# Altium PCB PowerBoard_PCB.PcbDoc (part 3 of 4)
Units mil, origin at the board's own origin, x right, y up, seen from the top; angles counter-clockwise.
Board outline 9251.97 x 3346.46 mil, 6 copper layers (Top Layer, Signal Layer 1, Signal Layer 2, Signal Layer 3, Signal Layer 4, Bottom Layer), stack 65.8 mil thick; 241 components, 145 nets, 894 pads, 120 vias.
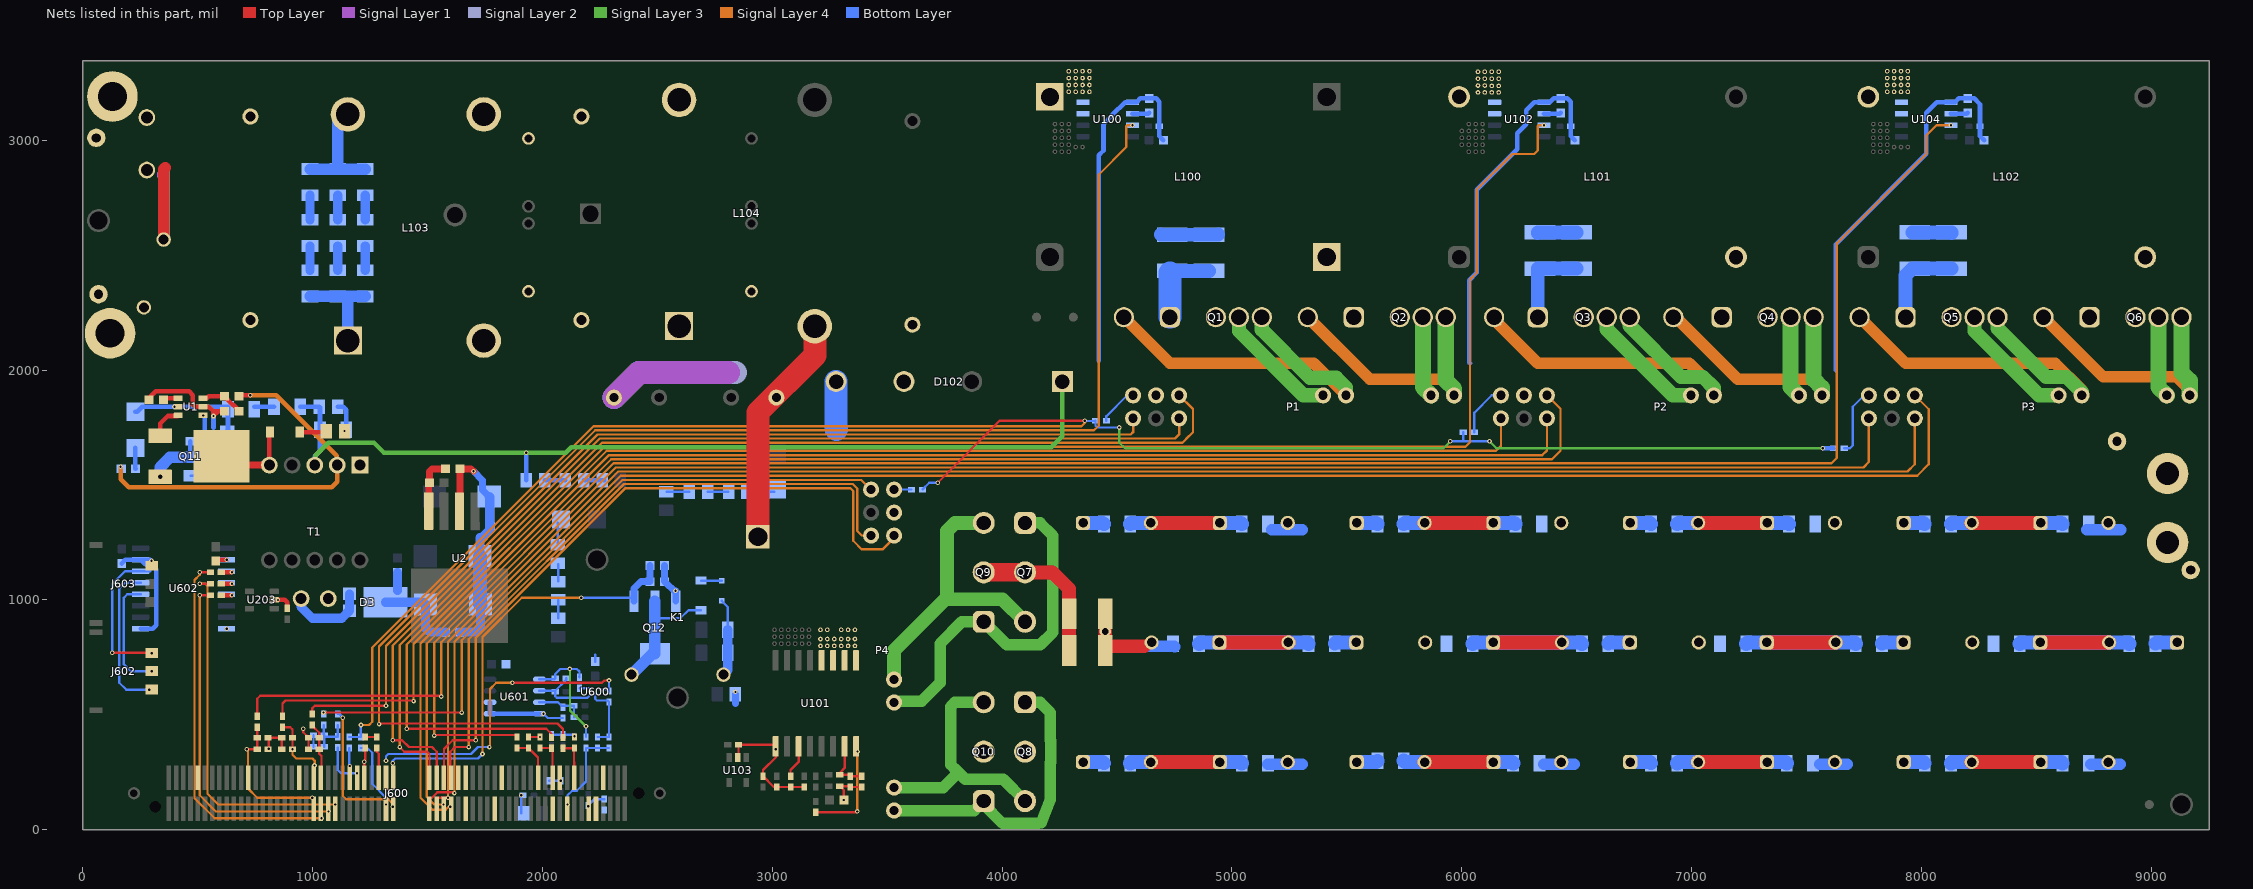
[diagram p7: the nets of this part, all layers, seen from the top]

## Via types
v1: diameter 20, hole 10, Top Layer to Bottom Layer, 116 vias
v2: diameter 30, hole 20, Top Layer to Bottom Layer, 3 vias
v3: diameter 50, hole 30, Top Layer to Bottom Layer, 1 vias

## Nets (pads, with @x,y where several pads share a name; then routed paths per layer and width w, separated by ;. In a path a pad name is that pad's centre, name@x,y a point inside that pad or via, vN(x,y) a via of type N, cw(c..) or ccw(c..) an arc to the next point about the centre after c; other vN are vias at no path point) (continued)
F1: C611.1 J600.77 R618.1 R631.2 | length 248.2
  Top Layer w10: R618.1@1000,456.38 1000,451.85 1029.97,421.88 R631.2@1029.97,400 C611.1@1029.97,349.84 1029.97,330.72 1040,320.69 1040,229.33 J600.77@1036.73,226.06
F2: C612.1 J600.79 R620.1 R632.2 | length 286.5
  Top Layer w10: R620.1@870,446.38 903.62,446.38 913.62,436.38 C612.1@913.62,400 v1(913.62,350)
  Signal Layer 4 w10: v1(913.62,350) 913.62,326.38 930,310 1000,310 1010,300 1010,280.98 v1(1009.02,280)
  Signal Layer 2 w10: v1(1009.02,280) v1@1010,280
F3: C613.1 J600.80 R624.1 R633.2 | length 652.9
  Top Layer w10: v1@720,350 C613.1@760,350 R633.2@760,400 R624.1@760,446.38 ; v1(1000,140) 1005.24,134.76 J600.80@1005.24,92.2
  Signal Layer 4 w10: v1@720,350 720,180 760,140 v1(1000,140)
  other v1: 715,350
F4: C618.1 R635.1 R636.2 R640.1 R643.2 | length 207.5
  Bottom Layer w10: R635.1@1050,456.38 1050,413.28 R636.2@1051.62,411.65 ; C618.1@1051.62,361.65 R636.2@1051.62,411.65 ; R643.2@1110,456.38 R640.1@1110,405.28 1058,405.28 R636.2@1051.62,411.65
G_AC_I: C602.1 J600.59 U600.6 | length 1363.2
  Top Layer w10: v1(1870,640) 2260,640 2270,650 v1(2290,650)
  Signal Layer 4 w10: v1(1770,360) 1772.48,362.48 1772.48,612.48 1800,640 v1(1870,640)
  Bottom Layer w10: v1(1320,300) 1320,320 1330,330 1690,330 1720,360 v1(1770,360) ; U600.6@2249.69,611.81 2281.81,611.81 C602.1@2290,603.62 v1(2290,650)
HVBUS: C1.1 C3.1 C5.1 C7.1 C9.1 C11.1 C13.1 C15.1 C17.1 C19.1 C21.1 C23.1 C27.1 C28.1 C29.1 C30.1 C31.1 C32.1 C33.1 C34.1 C36.1 D102.1 pad.1@9070,1550 Q1.1 Q3.1 Q5.1 Q7.2 Q9.2 R1.2 R3.2 R5.2 R7.2 R9.2 R11.2 R13.2 R15.2 R17.2 R19.2 R21.2 R23.2 R38.2 R40.2 R602.2 T1.3 TP100.1 | length 7000.1
  Top Layer w60: Q7.2@4100,1120 4220,1120 4291.26,1048.74 C27.1@4291.26,940 C28.1@4291.26,780
  Top Layer w80: Q9.2@3920,1120 Q7.2@4100,1120
  Signal Layer 3 w20: T1.3@1010,1586.69 1012.01,1588.7 1012.01,1626.63 1068.49,1683.11 1268.12,1683.11 1311.23,1640 v1(1930,1640) 2101.42,1640 2125.67,1664.25 4214.25,1664.25 4262.13,1712.13 D102.1@4262.13,1950
  Bottom Layer w20: R38.2@947.09,1840 C36.1@1030,1840 1032.91,1837.09 R40.2@1032.91,1740 1032.91,1647.54 1010,1624.62 T1.3@1010,1586.69 ; R602.2@1930,1520 v1(1930,1640)
  Bottom Layer w60: C17.1@4352.36,295 4437.91,295 R17.2@4442.91,290 ; C1.1@4352.36,1335 4437.91,1335 R1.2@4442.91,1330 ; C29.1@4730,2421.26 C29.1@4740,2431.26 C30.1@4900,2431.26 ; R15.2@5447.09,810 5452.09,815 C15.1@5540.64,815 ; C19.1@5542.36,295 5627.91,295 R19.2@5632.91,300 ; C3.1@5542.36,1335 5627.91,1335 R3.2@5632.91,1330 ; Q3.1@6330,2230 6330,2441.26 C32.1@6500,2441.26 ; R13.2@6637.09,810 6642.09,815 C13.1@6730.64,815 ; C21.1@6732.36,295 6817.91,295 R21.2@6822.91,290 ; C5.1@6732.36,1335 6817.91,1335 R5.2@6822.91,1330 ; R11.2@7827.09,810 7832.09,815 C11.1@7920.64,815 ; C23.1@7922.36,295 8007.91,295 R23.2@8012.91,290 ; C7.1@7922.36,1335 8007.91,1335 R7.2@8012.91,1330 ; Q5.1@7930,2230 7930,2411.26 7960,2441.26 C34.1@8130,2441.26 ; R9.2@9017.09,810 9022.09,815 C9.1@9110.64,815
  Bottom Layer w100: Q1.1@4730,2230 C29.1@4730,2421.26
L100_CS: R600.1 U100.7 | length 6095.1
  Top Layer w10: v1(1290,460) 1292.87,462.87 2066.34,462.87 2090,439.21 R600.1@2090,401.81
  Signal Layer 4 w10: v1(1290,460) 1290,797.87 2230,1737.87 4400,1737.87 4420,1757.87 4420,2850 4540,2970 4540,3060 4545,3065 v1(4567.28,3065)
L101_CS: R603.1 U102.7 | length 7592.1
  Top Layer w10: v1(1410,440) 2017.56,440 2040,417.56 R603.1@2040,401.81
  Signal Layer 4 w10: v1(1410,440) 1410,806.38 2270,1666.38 6015.67,1666.38 6035.29,1686 6035.29,2393.95 6065,2423.66 6065,2785 6220,2940 6314.91,2940 6330,2955.09 6330,3060 6335,3065 v1(6357.28,3065)
L102_CS: R608.1 U104.7 | length 8892.4
  Top Layer w10: v1(1530,410) 1532.87,412.87 1880.75,412.87 R608.1@1890,403.62
  Signal Layer 4 w10: v1(1530,410) 1530,814.25 2310,1594.25 7607.56,1594.25 7630.91,1617.6 7630.91,2550.91 8020,2940 8020,3020 8065,3065 v1(8127.28,3065)
NetC1_2: C1.2 C2.1 R1.1 R2.2 | length 1389.1
  Top Layer w62: C1.2@4647.64,1335 C2.1@4947.36,1335
  Signal Layer 1 w62: C1.2@4647.64,1335 C2.1@4947.36,1335
  Signal Layer 2 w62: C1.2@4647.64,1335 C2.1@4947.36,1335
  Bottom Layer w62: R1.1@4557.09,1330 4562.09,1335 C1.2@4647.64,1335 C2.1@4947.36,1335 5037.91,1335 R2.2@5042.91,1330
NetC3_2: C3.2 C4.1 R3.1 R4.2 | length 1389.1
  Top Layer w62: C3.2@5837.64,1335 C4.1@6137.36,1335
  Signal Layer 1 w62: C3.2@5837.64,1335 C4.1@6137.36,1335
  Signal Layer 2 w62: C3.2@5837.64,1335 C4.1@6137.36,1335
  Bottom Layer w62: R3.1@5747.09,1330 5752.09,1335 C3.2@5837.64,1335 C4.1@6137.36,1335 6227.91,1335 R4.2@6232.91,1330
NetC5_2: C5.2 C6.1 R5.1 R6.2 | length 1389.1
  Top Layer w62: C5.2@7027.64,1335 C6.1@7327.36,1335
  Signal Layer 1 w62: C5.2@7027.64,1335 C6.1@7327.36,1335
  Signal Layer 2 w62: C5.2@7027.64,1335 C6.1@7327.36,1335
  Bottom Layer w62: R5.1@6937.09,1330 6942.09,1335 C5.2@7027.64,1335 C6.1@7327.36,1335 7417.91,1335 R6.2@7422.91,1330
NetC7_2: C7.2 C8.1 R7.1 R8.2 | length 1388.4
  Top Layer w62: C7.2@8217.64,1335 C8.1@8517.36,1335
  Signal Layer 1 w62: C7.2@8217.64,1335 C8.1@8517.36,1335
  Signal Layer 2 w62: C7.2@8217.64,1335 C8.1@8517.36,1335
  Bottom Layer w62: R7.1@8127.09,1330 8132.09,1335 C7.2@8217.64,1335 C8.1@8517.36,1335 8607.22,1335 R8.2@8612.22,1330
NetC9_2: C9.2 C10.1 R9.1 R10.2 | length 1379.1
  Top Layer w62: C10.1@8515.64,815 C9.2@8815.36,815
  Signal Layer 1 w62: C10.1@8515.64,815 C9.2@8815.36,815
  Signal Layer 2 w62: C10.1@8515.64,815 C9.2@8815.36,815
  Bottom Layer w62: R10.2@8427.09,810 8432.09,815 C10.1@8515.64,815 C9.2@8815.36,815 8897.91,815 R9.1@8902.91,810
NetC11_2: C11.2 C12.1 R11.1 R12.2 | length 1379.1
  Top Layer w62: C12.1@7325.64,815 C11.2@7625.36,815
  Signal Layer 1 w62: C12.1@7325.64,815 C11.2@7625.36,815
  Signal Layer 2 w62: C12.1@7325.64,815 C11.2@7625.36,815
  Bottom Layer w62: R12.2@7237.09,810 7242.09,815 C12.1@7325.64,815 C11.2@7625.36,815 7707.91,815 R11.1@7712.91,810
NetC13_2: C13.2 C14.1 R13.1 R14.2 | length 1379.1
  Top Layer w62: C14.1@6135.64,815 C13.2@6435.36,815
  Signal Layer 1 w62: C14.1@6135.64,815 C13.2@6435.36,815
  Signal Layer 2 w62: C14.1@6135.64,815 C13.2@6435.36,815
  Bottom Layer w62: R14.2@6047.09,810 6052.09,815 C14.1@6135.64,815 C13.2@6435.36,815 6517.91,815 R13.1@6522.91,810
NetC15_2: C15.2 C16.1 R15.1 R16.2 | length 1378.4
  Top Layer w62: C16.1@4945.64,815 C15.2@5245.36,815
  Signal Layer 1 w62: C16.1@4945.64,815 C15.2@5245.36,815
  Signal Layer 2 w62: C16.1@4945.64,815 C15.2@5245.36,815
  Bottom Layer w62: R16.2@4857.85,810 4862.85,815 C16.1@4945.64,815 C15.2@5245.36,815 5327.91,815 R15.1@5332.91,810
NetC17_2: C17.2 C18.1 R17.1 R18.2 | length 1389.1
  Top Layer w62: C17.2@4647.64,295 C18.1@4947.36,295
  Signal Layer 1 w62: C17.2@4647.64,295 C18.1@4947.36,295
  Signal Layer 2 w62: C17.2@4647.64,295 C18.1@4947.36,295
  Bottom Layer w62: R17.1@4557.09,290 4562.09,295 C17.2@4647.64,295 C18.1@4947.36,295 5037.91,295 R18.2@5042.91,290
NetC19_2: C19.2 C20.1 R19.1 R20.2 | length 1379.1
  Top Layer w62: C19.2@5837.64,295 C20.1@6137.36,295
  Signal Layer 1 w62: C19.2@5837.64,295 C20.1@6137.36,295
  Signal Layer 2 w62: C19.2@5837.64,295 C20.1@6137.36,295
  Bottom Layer w62: R19.1@5747.09,300 5752.09,295 C19.2@5837.64,295 C20.1@6137.36,295 6217.91,295 R20.2@6222.91,290
NetC21_2: C21.2 C22.1 R21.1 R22.2 | length 1379.1
  Top Layer w62: C21.2@7027.64,295 C22.1@7327.36,295
  Signal Layer 1 w62: C21.2@7027.64,295 C22.1@7327.36,295
  Signal Layer 2 w62: C21.2@7027.64,295 C22.1@7327.36,295
  Bottom Layer w62: R21.1@6937.09,290 6942.09,295 C21.2@7027.64,295 C22.1@7327.36,295 7407.91,295 R22.2@7412.91,290
NetC23_2: C23.2 C24.1 R23.1 R24.2 | length 1389.1
  Top Layer w62: C23.2@8217.64,295 C24.1@8517.36,295
  Signal Layer 1 w62: C23.2@8217.64,295 C24.1@8517.36,295
  Signal Layer 2 w62: C23.2@8217.64,295 C24.1@8517.36,295
  Bottom Layer w62: R23.1@8127.09,290 8132.09,295 C23.2@8217.64,295 C24.1@8517.36,295 8607.91,295 R24.2@8612.91,290
NetC36_2: C36.2 R40.1 R41.2 | length 129.4
  Bottom Layer w20: C36.2@1110,1840 1134,1840 1147.09,1826.91 R40.1@1147.09,1740
  other v1: 1140,1734.57
NetC37_1: C37.1 R42.1 U1.4 | length 192.5
  Top Layer w20: U1.4@524.13,1802.6 v1(525.31,1802.6)
  Bottom Layer w20: v1(525.31,1802.6) 531.5,1796.41 R42.1@531.5,1690 531.5,1640 C37.1@550,1621.5
NetC38_1: C38.1 C39.1 D3.3 L1.1 | length 450.8
  Bottom Layer w40: D3.3@1318.39,990 1482.4,990 C39.1@1492.4,980 1492.4,877.6 1510,860 C38.1@1578.5,860 ; D3.3@1370,1041.61 L1.1@1370,1118.5
NetC107_1: C107.1 C110.1 L103.3 L104.2
NetC109_1: C109.1 F100.1 L103.2 R105.2 R106.2 R107.2 RV100.2 | length 2189.4
  Top Layer w50: RV100.2@353.31,2567.64 353.31,2873.31 360,2880
  Signal Layer 1 w50: 350,2850 353.31,2846.69 RV100.2@353.31,2567.64
  Signal Layer 3 w50: RV100.2@353.31,2567.64 353.31,2860
  Signal Layer 4 w50: RV100.2@353.31,2567.64 353.31,2846.69
  Signal Layer 2 w50: RV100.2@353.31,2567.64 353.31,2860
  Bottom Layer w50: 350,2850 353.31,2846.69 RV100.2@353.31,2567.64 ; R107.2@990,2874.17 R106.2@1110,2874.17 ; L103.2@1110,3077.24 R106.2@1110,2874.17 ; R105.2@1230,2874.17 R106.2@1110,2874.17
NetC109_2: C109.2 L103.1 pad.1@120,2160 R111.1 R112.1 R113.1 RV100.1 TP103.1 | length 368.6
  Bottom Layer w50: R113.1@990,2320 R112.1@1110,2320 R111.1@1230,2320 ; L103.1@1154.57,2187.09 1154.57,2315.67
NetC110_2: C110.2 C112.2 L103.4 L104.1
NetC113_2: C113.2 C114.2 K1.1 L104.4 RT100.1 RT101.1 | length 2133.6
  Top Layer w100: K1.1@2938.15,1275.04 2938.15,1815.73 3185.28,2062.85 L104.4@3185.28,2187.87
  Signal Layer 1 w100: RT100.1@2311.57,1880 2421.57,1990 2810.46,1990
  Signal Layer 2 w100: RT100.1@2311.57,1880 2421.57,1990 2840,1990
NetC116_1: C116.1 U100.6 | length 74.2
  Bottom Layer w20: U100.6@4567.28,3115 4636.5,3115 C116.1@4640,3118.5
NetC124_1: C124.1 R117.2 R124.2 U101.15 | length 230.9
  Top Layer w10: U101.15@3315,362.99 3315,269 3293.62,247.62 R117.2@3293.62,240 3333.62,240 R124.2@3340,233.62 C124.1@3390,233.62
NetC125_1: C125.1 U102.6 | length 74.2
  Bottom Layer w20: U102.6@6357.28,3115 6426.5,3115 C125.1@6430,3118.5
NetC127_1: C127.1 U101.11 | length 143.9
  Top Layer w10: C127.1@3080,233.62 3080,260 3115,295 U101.11@3115,362.99
NetC134_1: C134.1 U104.6 | length 74.2
  Bottom Layer w20: U104.6@8127.28,3115 8196.5,3115 C134.1@8200,3118.5
NetC601_1: C601.1 J600.15 R600.2 | length 243.6
  Top Layer w10: R600.2@2090,354.57 2138.19,354.57 2138.19,226.97 J600.15@2139.09,226.06 ; J600.15@2140,226.97 2140,293.5
NetC603_2: C603.2 J600.12 R604.1 | length 91.5
  Bottom Layer w10: v1(2199.33,102.44) 2199.33,105.71 R604.1@2200,106.38 2227.24,133.62 C603.2@2270,133.62 ; R604.1@2202.86,102.44 2202.86,97.14 R604.1@2203.52,97.14
NetC604_1: C604.1 J600.21 R603.2 | length 181.2
  Top Layer w10: C604.1@1990,356.38 2038.19,356.38 R603.2@2040,354.57 2044.61,349.96 J600.21@2044.61,226.06
NetC607_1: C607.1 J600.25 R608.2 | length 197.6
  Top Layer w10: R608.2@1890,356.38 C607.1@1940,356.38 1981.61,314.76 J600.25@1981.61,226.06
NetC608_1: C608.1 J600.18 R611.1 R613.2 | length 391.2
  Bottom Layer w10: v1(2110,110) 2110,150 2130,170 2150,170 2190,210 R611.1@2190,356.38 C608.1@2290,356.38
NetD1_2: D1.2 R37.2 | length 91.9
  Bottom Layer w20: D1.2@230,1661.26 230,1571.5 R37.2@231.5,1570
NetD2_1: D2.1 R41.1 | length 117.4
  Top Layer w20: D2.1@944.47,1730 1055.43,1730 R41.1@1060,1734.57
NetD2_2: D2.2 Q11.4 T1.5 | length 367.9
  Top Layer w20: T1.5@813.15,1586.69 813.15,1727.62 D2.2@815.53,1730
  Top Layer w30: Q11.4@605.38,1625 643.69,1586.69 T1.5@813.15,1586.69
NetD3_1: D3.1 D3.2 T1.B | length 355.1
  Bottom Layer w40: T1.B@950.94,1005.98 950,1005.04 950,970 1000,920 1127.83,920 D3.1@1161.61,953.78 D3.2@1161.61,1026.22
NetD100_1: D100.1 R102.2 | length 120.2
  Bottom Layer w10: R102.2@2890,1470 D100.1@3010.24,1470
NetD104_1: D104.1 R119.2 | length 95.4
  Bottom Layer w10: R119.2@2066.61,1240 D104.1@2066.61,1335.35
NetD105_1: D105.1 K1.4 Q12.2 Q12.4 | length 582.5
  Bottom Layer w10: 2490,920 2600,920 2635.53,955.53 D105.1@2690,955.53
  Bottom Layer w50: K1.4@2388.15,675.04 2478.94,765.83 Q12.4@2490,765.83 2490,920 Q12.2@2490,994.17
NetD105_2: D105.2 D106.2 | length 88.8
  Bottom Layer w10: D105.2@2691.16,1083.31 D106.2@2780,1083.31
NetD106_1: D106.1 K1.5 R118.1 R120.1 | length 340.7
  Bottom Layer w10: D106.1@2780,996.69 2807.09,969.61 R120.1@2807.09,870
  Bottom Layer w40: K1.5@2788.15,675.04 2807.09,693.98 R118.1@2807.09,770 R120.1@2807.09,870
NetF100_2: F100.2 pad.1@130,3190 TP101.1
NetJ600_58: J600.58 R643.1 | length 614.6
  Signal Layer 4 w10: v1(1132.09,487.13) 1132.09,147.91 1147.13,132.87 1329.47,132.87 1350,112.35 v1(1350,100)
  Bottom Layer w10: R643.1@1110,503.62 1118.03,503.62 1132.09,489.57 v1(1132.09,487.13)
NetJ600_60: J600.60 R642.1 | length 308.9
  Bottom Layer w10: R642.1@1210,356.38 1238.92,356.38 1260,335.29 1260,200 1320,140 v1(1320,110)
NetJ600_61: J600.61 R630.2 | length 133.9
  Top Layer w10: R630.2@1280,356.38 1280,340 1288.7,331.3 J600.61@1288.7,226.06
NetJ600_67: J600.67 R640.2 | length 188.1
  Bottom Layer w10: R640.2@1110,358.03 1110,260 1124.21,245.79 v1(1194.21,245.79)
NetJ600_69: J600.69 R641.2 | length 80.2
  Bottom Layer w10: R641.2@1160,356.38 1160,280 v1(1162.72,277.28)
NetJ602_1: J602.1 U602.14 | length 659.3
  Top Layer w10: v1(130,770) 299.76,770 v1(301.02,768.74)
  Bottom Layer w10: v1(130,770) 130,1070 185,1125 U602.14@252.99,1125 295,1125
NetJ602_2: J602.2 U602.12 | length 502.7
  Bottom Layer w10: U602.12@252.99,1025 195,1025 180,1010 180,720 210,690 v1(301.02,690)
NetJ602_3: J602.3 U602.13 | length 655.8
  Bottom Layer w10: U602.13@252.99,1075 185,1075 160,1050 160,640 190,610 v1(290,610)
NetL100_2: L100.2 pad.2@4380,3210 pad.3@4350,3210 pad.4@4320,3210 pad.5@4290,3210 pad.7@4380,3240 pad.8@4350,3240 pad.9@4320,3240 pad.10@4290,3240 pad.12@4380,3270 pad.13@4350,3270 pad.14@4320,3270 pad.15@4290,3270 pad.16@4290,3300 pad.17@4320,3300 pad.18@4350,3300 pad.19@4380,3300 U100.3 U100.4
NetL100_4: L100.4 Q1.2 Q2.1
NetL101_2: L101.2 pad.5@6070,3297.52 pad.6@6100,3297.52 pad.7@6130,3297.52 pad.8@6160,3297.52 pad.9@6070,3267.52 pad.10@6100,3267.52 pad.11@6130,3267.52 pad.12@6160,3267.52 pad.13@6070,3237.52 pad.14@6100,3237.52 pad.15@6130,3235.79 pad.16@6160,3235.79 pad.17@6070,3207.52 pad.18@6100,3207.52 pad.19@6130,3207.52 pad.20@6160,3207.5 U102.3 U102.4
NetL101_4: L101.4 Q3.2 Q4.1
NetL102_2: L102.2 pad.1@7850,3300 pad.2@7880,3300 pad.3@7910,3300 pad.4@7940,3300 pad.5@7850,3270 pad.6@7880,3270 pad.7@7910,3270 pad.8@7940,3270 pad.9@7850,3240 pad.10@7880,3240 pad.11@7910,3240 pad.12@7940,3240 pad.13@7850,3210 pad.14@7880,3210 pad.15@7910,3210 pad.16@7940,3210 U104.3 U104.4
NetL102_4: L102.4 Q5.2 Q6.1
NetQ11_1: Q11.1 U1.3 | length 145.6
  Top Layer w20: Q11.1@337.67,1714.77 337.67,1767.67 370,1800 413.27,1800 U1.3@415.87,1802.6
NetQ11_3: Q11.3 R42.2 R43.2 | length 262.9
  Bottom Layer w20: R42.2@468.5,1690 468.5,1621.5 R43.2@470,1620
  Bottom Layer w50: v2(337.67,1535.24) 337.67,1577.67 380,1620 R43.2@470,1620
NetR25_2: R25.2 U1.1 | length 67.4
  Top Layer w20: R25.2@351.5,1870 358.9,1877.4 U1.1@415.87,1877.4
NetR35_1: R35.1 R36.2 U1.6 | length 191.9
  Top Layer w20: U1.6@524.13,1877.4 540.08,1877.4 548.94,1886.26 R35.1@618.5,1886.26 618.5,1883.66 652.48,1849.69 655.08,1849.69 681.5,1823.27 R36.2@681.5,1820
NetR35_2: R35.2 R37.1 T1.2 | length 1671.2
  Top Layer w20: R35.2@681.5,1886.26 686.26,1886.26 690,1890 v1(730,1890)
  Signal Layer 4 w20: v1(165.55,1580) 165.55,1525.55 201.1,1490 1084.76,1490 1108.43,1513.66 T1.2@1108.43,1586.69 1106.42,1588.7 1106.42,1626.63 843.05,1890 v1(730,1890)
NetR38_1: R38.1 R39.2 | length 85.8
  Bottom Layer w20: R39.2@747.09,1840 R38.1@832.91,1840
NetR44_1: R44.1 R45.2 U2.5 | length 244.8
  Top Layer w30: U2.5@1506.14,1386.06 R44.1@1506.14,1507.64 ; R44.1@1508.5,1510 1508.5,1558.5 1520,1570 R45.2@1578.5,1570
NetR100_2: R100.2 R101.1 | length 100
  Bottom Layer w10: R100.2@2540,1470 R101.1@2640,1470
NetR101_2: R101.2 R102.1 | length 90
  Bottom Layer w10: R101.2@2720,1470 R102.1@2810,1470
NetR105_1: R105.1 R108.2 | length 105.8
  Bottom Layer w40: R108.2@1230,2654.17 R105.1@1230,2760
NetR106_1: R106.1 R109.2 | length 105.8
  Bottom Layer w40: R109.2@1110,2654.17 R106.1@1110,2760
NetR107_1: R107.1 R110.2 | length 105.8
  Bottom Layer w40: R110.2@990,2654.17 R107.1@990,2760
NetR108_1: R108.1 R111.2 | length 105.8
  Bottom Layer w40: R111.2@1230,2434.17 R108.1@1230,2540
NetR109_1: R109.1 R112.2 | length 105.8
  Bottom Layer w40: R112.2@1110,2434.17 R109.1@1110,2540
NetR110_1: R110.1 R113.2 | length 105.8
  Bottom Layer w40: R113.2@990,2434.17 R110.1@990,2540
NetR116_1: R116.1 U101.16 | length 442.3
  Top Layer w10: R116.1@3190,76.38 3366.38,76.38 v1(3370,80)
  Signal Layer 4 w10: v1(3370,80) 3370,339.25 v1(3371.1,340.35)
NetR119_1: R119.1 R121.2 | length 76.6
  Bottom Layer w10: R121.2@2070.05,1080 R119.1@2070.05,1156.57
NetR121_1: R121.1 R123.2 | length 80
  Bottom Layer w10: R123.2@2070,920 R121.1@2070.05,1000
NetR601_1: R601.1 R606.1 R611.2 U601.1 | length 544.1
  Signal Layer 3 w10: v1(2120,700) 2120.59,699.41 2120.59,519.41 v1(2190,450)
  Bottom Layer w10: U601.1@1987.28,655 R606.1@2051.38,655 ; R606.1@2056.38,660 2056.38,678.03 2078.35,700 v1(2120,700) 2150,700 2161.82,688.18 R601.1@2161.82,663.62 R601.1@2160,665.45 ; R611.2@2190,403.62 2190,440
NetR601_2: R601.2 U600.4 | length 43.9
  Bottom Layer w10: R601.2@2161.82,616.38 2205.75,616.38
NetR602_1: R602.1 R605.1 | length 90
  Bottom Layer w20: R602.1@2010,1520 R605.1@2100,1520
NetR605_2: R605.2 R607.1 | length 90
  Bottom Layer w20: R605.2@2180,1520 R607.1@2270,1520
NetR606_2: R606.2 R610.2 U600.3 U601.2 | length 332
  Bottom Layer w10: U601.2@1987.28,605 2051.38,605 R610.2@2056.38,600 ; R606.2@2103.62,660 2103.62,651.97 2056.38,604.72 R610.2@2056.38,600 ; U600.3@2210.32,588.19 2196.81,574.68 2062.57,574.68 2056.38,580.88 R610.2@2056.38,600
NetR612_1: R612.1 R614.1 R615.2 U601.3 | length 207.1
  Bottom Layer w10: U601.3@1987.28,555 2068.62,555 2083.62,540 R612.1@2138.2,540 R614.1@2138.2,490
NetR644_2: R644.2 U602.3 | length 46.4
  Top Layer w20: R644.2@603.62,1120 v1(650,1120)
NetR645_2: R645.2 U602.4 | length 46.4
  Top Layer w20: R645.2@603.62,1070 v1(650,1070)
NetR646_2: R646.2 U602.5 | length 46.4
  Top Layer w20: R646.2@603.62,1020 v1(650,1020)
PFC_1H_G: P1.8 pad.6@4530,2230 Q1.4 | length 1665.5
  Signal Layer 3 w62: Q1.4@5130,2230 5130,2175.44 5339.44,1966 5454,1966 5496,1924 P1.8@5496,1890
  Signal Layer 4 w50: pad.6@4530,2230 4730,2030 5356,2030 P1.8@5496,1890
PFC_1H_S: P1.7 Q1.3 | length 542
  Signal Layer 3 w62: Q1.3@5030,2230 5030,2170 5310,1890 P1.7@5396,1890
PFC_1L_G: P1.10 pad.5@5330,2230 Q2.4 | length 1151.7
  Signal Layer 3 w70: Q2.4@5930,2230 5930,1954.53 5966,1918.53 P1.10@5966,1890
  Signal Layer 4 w50: pad.5@5330,2230 5600,1960 5930,1960 5966,1924 P1.10@5966,1890
PFC_1L_S: P1.9 Q2.3 | length 354.9
  Signal Layer 3 w70: Q2.3@5830,2230 5830,1926 P1.9@5866,1890
PFC_2H_G: P2.8 pad.3@6140,2230 Q3.4 | length 1673.6
  Signal Layer 3 w62: Q3.4@6730,2230 6730,2192.82 6952.81,1970 7048.58,1970 7096,1922.58 P2.8@7096,1890
  Signal Layer 4 w50: pad.3@6130,2230 6330,2030 6988.58,2030 7096,1922.58 P2.8@7096,1890
PFC_2H_S: P2.7 Q3.3 | length 537.5
  Signal Layer 3 w62: Q3.3@6630,2230 6630,2177.58 6917.58,1890 P2.7@6996,1890
PFC_2L_G: P2.10 pad.2@6920,2230 Q4.4 | length 1157.8
  Signal Layer 3 w50: Q4.4@7530,2230 Q4.4@7536,2224
  Signal Layer 3 w70: Q4.4@7530,2230 7530,1960 7566,1924 P2.10@7566,1890
  Signal Layer 4 w50: pad.2@6930,2230 7200,1960 7526,1960 7566,1920 P2.10@7566,1890
PFC_2L_S: P2.9 Q4.3 | length 369.1
  Signal Layer 3 w50: Q4.3@7430,2230 Q4.3@7440,2220
  Signal Layer 3 w70: Q4.3@7430,2230 7430,1926 P2.9@7466,1890
PFC_3H_G: P3.8 pad.1@7730,2230 Q5.4 | length 1664.3
  Signal Layer 3 w62: Q5.4@8330,2230 8330,2181.61 8541.61,1970 8630,1970 8696,1904 P3.8@8696,1890
  Signal Layer 4 w50: pad.1@7730,2230 7930,2030 8580,2030 8696,1914 P3.8@8696,1890
PFC_3H_S: P3.7 Q5.3 | length 542
  Signal Layer 3 w62: Q5.3@8230,2230 8230,2170 8510,1890 P3.7@8596,1890
PFC_3L_G: P3.10 pad.1@8530,2230 Q6.4 | length 1154.3
  Signal Layer 3 w50: Q6.4@9130,2230 Q6.4@9136,2224
  Signal Layer 3 w70: Q6.4@9130,2230 9130,1990 9166,1954 P3.10@9166,1890
  Signal Layer 4 w50: pad.1@8530,2230 8790,1970 9110,1970 9166,1914 P3.10@9166,1890
PFC_3L_S: P3.9 Q6.3 | length 354.9
  Signal Layer 3 w70: Q6.3@9030,2230 9030,1926 P3.9@9066,1890
PFC_4H_G: P4.8 Q7.1 Q9.1 | length 1562.7
  Signal Layer 3 w50: P4.8@3530,554 3536,560 3650,560 3730,640 3730,810 3825,905 Q9.1@3920,905 4020,805 4166.2,805 4220,858.8 4220,1280 4165,1335 Q7.1@4100,1335
PFC_4H_S: D102.3 P4.7 pad.1@3300,830 pad.2@3270,830 pad.3@3330,830 pad.4@3300,870 pad.5@3330,870 pad.6@3360,870 pad.7@3210,830 pad.8@3240,830 pad.9@3360,830 pad.10@3210,870 pad.11@3240,870 pad.13@3210,800 pad.14@3240,800 pad.15@3270,800 pad.16@3300,800 pad.17@3330,800 pad.18@3360,800 Q7.3 Q8.2 Q9.3 Q10.2 U101.1 U101.2 U101.3 U101.4 | length 1299.3
  Signal Layer 3 w60: P4.7@3530,654 3530,780 3760,1010 ; Q9.3@3920,1335 3795,1335 3760,1300 3760,1010 ; Q7.3@4100,905 4002.4,1002.6 3767.4,1002.6 3760,1010
PFC_4L_G: P4.10 Q8.1 Q10.1 | length 1312.2
  Signal Layer 3 w50: P4.10@3530,84 3879,84 Q10.1@3920,125 3920,110 4002.07,27.93 4157.93,27.93 ; Q8.1@4100,555 4165,555 4210,510 4210,388.96 4212.4,386.56 4212.4,293.44 4210,291.04 4210,130 4170,30
PFCG_1H: J600.53 P1.3 | length 4587.2
  Top Layer w10: v1(1350,390) 1390,390 1420,360 1520,360 1540.67,339.33 J600.53@1540.67,226.06
  Signal Layer 4 w10: v1(1350,390) 1350,802.13 2250,1702.13 4752.13,1702.13 4770,1720 P1.3@4770,1770
PFCG_1L: J600.55 P1.6 | length 4709
  Top Layer w10: v1(1380,360) 1400,340 1500,340 1509.17,330.83 J600.55@1509.17,226.06
  Signal Layer 4 w10: v1(1380,360) 1380,804.25 2260,1684.25 4784.25,1684.25 4812.87,1712.87 4813.66,1712.87 4830,1729.21 4830,1830 P1.6@4770,1890
PFCG_2H: J600.50 P2.3 | length 6195.2
  Signal Layer 4 w10: v1(1600,100) 1592.35,100 1579.47,87.13 1522.87,87.13 1470,140 1470,810 2290,1630 6350,1630 6370,1650 P2.3@6370,1770
PFCG_2L: J600.52 P2.6 | length 6297.7
  Signal Layer 4 w10: v1(1570,110) 1530,110 1497.24,142.76 1497.24,809.37 2300,1612.13 6392.13,1612.13 6428.75,1648.75 6428.75,1831.25 P2.6@6370,1890
PFCG_3H: J600.54 P3.3 | length 7649.7
  Top Layer w10: J600.54@1540.67,92.2 1540.67,130.67 1550,140 v1(1590,140)
  Signal Layer 4 w10: v1(1590,140) 1590,818.5 2330,1558.5 7938.5,1558.5 7970,1590 P3.3@7970,1770
PFCG_3L: J600.56 P3.6 | length 7875.9
  Top Layer w10: J600.56@1509.17,92.2 1509.17,129.17 1542.87,162.87 1615,162.87 v1(1617.87,160)
  Signal Layer 4 w10: v1(1617.87,160) 1617.87,817.87 2340,1540 7980.63,1540.63 8030.81,1590.81 8030.81,1829.19 P3.6@7970,1890
PFCG_4H: J600.49 P4.3 | length 2903.5
  Top Layer w10: J600.49@1603.66,226.06 1600,229.72 1600,340 1620,360 v1(1680,360)
  Signal Layer 4 w10: v1(1680,360) 1680,829.44 2354.81,1504.25 3350,1504.25 3370,1484.25 3370,1300 3390,1280 P4.3@3430,1280
PFCG_4L: J600.51 P4.6 | length 3081.7
  Top Layer w10: J600.51@1572.17,226.06 1572.17,352.17 1610,390 v1(1710,390)
  Signal Layer 4 w10: v1(1710,390) 1710,834.17 2362.21,1486.38 3340,1486.38 3352.13,1474.25 3352.13,1257.87 3390,1220 3480,1220 3530,1270 P4.6@3530,1280
PGND: C2.2 C4.2 C6.2 C8.2 C10.2 C12.2 C14.2 C16.2 C18.2 C20.2 C22.2 C24.2 C27.2 C28.2 C29.2 C30.2 C31.2 C32.2 C33.2 C34.2 C35.2 C37.2 C38.2 C39.2 C40.2 C41.2 C42.2 C111.2 C115.2 C116.2 C118.2 C119.2 C120.2 C121.2 C122.2 C123.2 C124.2 C125.2 C127.2 C128.2 C129.1 C130.2 C131.2 C132.2 C133.2 C134.2 C600.1 C601.2 C602.2 C603.1 C604.2 C605.1 C606.2 C607.2 C608.2 C609.2 C610.2 C611.2 C612.2 C613.2 C614.2 C615.1 C617.2 C618.2 D102.4 J600.7 J600.10 J600.19 J600.22 J600.35 J600.38 J600.46 J600.47 J600.65 J600.83 J600.97 J600.111 P1.5 P2.5 P3.5 P4.5 P4.9 pad.2@9070,1250 Q2.2 Q4.2 Q6.2 Q8.3 Q10.3 Q12.3 R2.1 R4.1 R6.1 R8.1 R10.1 R12.1 R14.1 R16.1 R18.1 R20.1 R22.1 R24.1 R25.1 R36.1 R43.1 R45.1 R122.1 R124.1 R609.1 R613.1 R615.1 R616.1 R617.1 R631.1 R632.1 R633.1 R636.1 T1.1 T1.A TP102.1 U1.5 U2.3 U100.5 U101.9 U102.5 U103.2 U104.5 U203.2 U600.2 U601.4 U601.5 U601.6 U602.2 U602.8 | length 12266.1
  Top Layer w10: C613.2@807.24,350 v1(810,352.76) 810,397.24 R633.1@807.24,400 C612.2@866.38,400 R632.1@866.38,350 ; v1(960,440) 960,424.65 982.72,401.93 R631.1@982.72,400 C611.2@982.72,349.84 ; J600.65@1225.71,226.06 v1(1225.71,295.71) ; v1@1230,295.71 C617.2@1230,356.38 ; C607.2@1940,403.62 v1(1990,403.62) ; C601.2@2140,403.62 v1(2140,407.72) ; J600.10@2230,100 2233.62,96.38 J600.10@2237.36,96.38 ; U103.2@2853.62,317.76 C133.2@2853.62,370 U101.9@3007.99,370 ; U101.9@3015,362.99 v1(3015,350) 3015,315 2960,260 C131.2@2960,233.62 3007.24,186.38 C128.2@3020,186.38 C127.2@3080,186.38 C129.1@3140,186.38 ; v1(3311.5,130) 3311.5,172.13 C118.2@3293.62,190 R124.1@3336.38,190 ; R124.1@3340,186.38 C124.2@3390,186.38
  Top Layer w20: R25.1@288.5,1870 288.5,1877.05 318.54,1907.09 463.94,1907.09 480,1891.02 480,1849.68 489.68,1840 U1.5@524.13,1840 550,1840 570,1820 ; C615.1@580,1168.5 586.5,1175 v1(627.01,1175) ; R36.1@618.5,1820 590,1820 ; U203.2@834.13,1000 v1(850,1000) 880,1000 890,990 C614.2@890,963.62 ; 570,1820 590,1820 ; 570,1820 v1(570,1800) 590,1820
  Top Layer w30: U2.3@1641.5,1387.56 R45.1@1641.5,1570 1690.55,1570 v1(1700.55,1560)
  Top Layer w60: v3(4448.74,863.23) C28.2@4448.74,780 4467.66,798.92 4618.18,798.92
  Signal Layer 3 w50: P4.9@3530,184 3744,184 3803,243 3803,257 ; Q10.3@3920,555 3795,555 3776,536 3776,284 3803,257 ; Q8.3@4100,125 4005,220 3840,220 3803,257
  Bottom Layer w10: R43.1@470,1540 531.5,1540 C37.2@550,1558.5 608.77,1558.5 630,1579.74 ; C618.2@1004.38,361.65 R636.1@1004.38,411.65 ; R609.1@1908.5,71.5 v1(1908.5,150) ; U601.4@1987.28,505 v1(2005,505) 2023.62,486.38 R615.1@2090,486.38 ; C610.2@2030,213.62 R617.1@2080,213.62 2080,237.88 2079.88,238 v1(2079.88,213.62) ; C609.2@2040,413.62 R616.1@2090,413.62 2137.24,413.62 2140,416.38 v1(2140,407.72) ; U600.2@2230,588.19 2230,570 2237.13,562.87 2283.5,562.87 C602.2@2290,556.38 C608.2@2290,403.62 R613.1@2240,403.62 ; C600.1@2230,731.5 2230,761.02
  Bottom Layer w20: 570,1750 v1(570,1800) ; U601.6@1772.72,555 U601.5@1772.72,505 U601.4@1987.28,505 ; 4420,2040 4420,2933.54 4441.26,2954.8 4441.26,3070 4480,3108.74 4480,3110 4535,3165 U100.5@4567.28,3165 4585,3165 4601.5,3181.5 C116.2@4640,3181.5 4669.77,3181.5 4683.62,3167.64 C111.2@4683.62,3060 4683.62,3017.87 C115.2@4701.5,3000 ; 6035.29,2030 6032.75,2032.55 6032.75,2391.41 6065.51,2424.17 6065.51,2558.98 6065,2559.49 6065,2785 6240,2960 6240,3030 6280,3070 6280,3130 6315,3165 U102.5@6357.28,3165 6382.64,3165 6399.13,3181.5 C125.2@6430,3181.5 6458.5,3181.5 6473.62,3166.38 C121.2@6473.62,3060 6473.62,3017.87 C123.2@6491.5,3000 ; 7625.91,2000 7625.91,2545.91 8020,2940 8020,3120 8065,3165 U104.5@8127.28,3165 8145,3165 8161.5,3181.5 C134.2@8200,3181.5 8228.5,3181.5 8253.62,3156.38 C130.2@8253.62,3060 8253.62,3017.87 C132.2@8271.5,3000
  Bottom Layer w30: v1(1700.55,1560) 1740,1520.55 1740,1479.09 C42.2@1769.09,1450 ; R122.1@2531.5,1150 2531.5,1081.22 Q12.3@2580.55,1032.16 ; v1(2579.5,1040) 2580.55,1038.94 Q12.3@2580.55,1032.16 ; Q12.3@2580.55,994.17 Q12.3@2580.55,1032.16 ; 2840,550 C122.2@2840,590
  Bottom Layer w40: C38.2@1641.5,860 1710.39,860 1730.59,880.2 C39.2@1730.59,980 ; C40.2@1729.09,1190 1729.09,1270.91 1737.22,1270.91 1771.5,1305.19 C41.2@1771.5,1320 1771.5,1447.6 C42.2@1769.09,1450
  Bottom Layer w50: 4618.18,798.92 4748.56,798.92 R16.1@4751.85,795.63 ; R18.1@5156.02,285.63 5305.79,285.63 ; R2.1@5172.96,1305.63 5305.79,1305.63 ; R20.1@6356.02,285.63 6489.55,285.63 ; 7556.02,285.63 7677.05,285.63 ; R8.1@8718.22,1305.63 8864.91,1305.63 ; R24.1@8736.02,285.63 8864.55,285.63
  Bottom Layer w60: C40.2@1729.09,1190 1729.09,981.5 C39.2@1730.59,980 ; C29.2@4690,2590 4691.26,2588.74 C29.2@4740,2588.74 C30.2@4900,2588.74 4938.74,2588.74 C30.2@4940,2590 ; C31.2@6330,2594.82 6330,2598.74 C32.2@6500,2598.74 ; C33.2@7960,2598.74 C34.2@8130,2598.74 C34.2@8130,2594.82
  Bottom Layer w100: D102.4@3277.87,1950 3277.87,1744.37 3280,1742.24
  other v1: 2840,600 627.01,875
PRI_FAULT: J600.74 R645.1 | length 1563.9
  Top Layer w10: v1(510,1070) R645.1@556.38,1070
  Signal Layer 4 w10: v1(510,1070) 534.5,1070 543.5,1061 543.5,156.5 590,110 v1(1100,110)
PWM_DEBUG: C617.1 R630.1 | length 50
  Top Layer w10: C617.1@1230,403.62 R630.1@1280,403.62
RELAY_CTRL: C120.1 J600.57 Q12.1 R122.2 | length 1865.2
  Signal Layer 4 w10: v1(1740,330) 1740,838.89 1911.11,1010 v1(2170,1010)
  Bottom Layer w10: v1(1350,290) 1350,300 1360,310 1720,310 v1(1740,330) ; v1(2170,1010) 2383.62,1010 Q12.1@2399.45,994.17
  Bottom Layer w30: Q12.1@2399.45,994.17 2399.45,1049.45 2430,1080 C120.1@2468.5,1080 R122.2@2468.5,1150
RST: R621.2 R625.2 R626.2 R634.2 R641.1 R642.2 | length 8238.8
  Top Layer w10: v1(3720,1510) 3990,1780 v1(4360,1780)
  Signal Layer 3 w10: v1(4510,1750) 4510,1684.25 4534.25,1660 5920,1660 v1(5950,1690) ; v1(6120,1690) 6150,1660 v1(7570,1660)
  Signal Layer 4 w10: v1(1211.5,456) 1246,456 1260,470 1260,793.15 2222.6,1755.75 4345.75,1755.75 4360,1770 v1(4360,1780)
  Bottom Layer w10: R641.1@1160,403.62 R642.2@1210,403.62 1210,454.5 v1(1211.5,456) ; R634.2@3653.62,1480 3683.62,1510 v1(3720,1510) ; 4371.38,1778.62 4405,1778.62 R621.2@4406.38,1780 4406.38,1758.12 4414.5,1750 v1(4510,1750) ; v1(5950,1690) 6010.29,1690 ; R625.2@6006.38,1730 6006.38,1693.91 6010.29,1690 ; v1(6120,1690) 6010.29,1690
  Bottom Layer w20: v1(7570,1660) R626.2@7616.38,1660
RST_1: P1.4 R621.1 | length 173.1
  Bottom Layer w10: R621.1@4453.62,1780 4453.62,1799.12 4544.5,1890 P1.4@4570,1890
RST_2: P2.4 R625.1 | length 231.6
  Bottom Layer w10: R625.1@6053.62,1730 6053.62,1813.62 6130,1890 P2.4@6170,1890
RST_3: P3.4 R626.1 | length 300.1
  Bottom Layer w10: R626.1@7663.62,1660 7688,1660 7700,1672 7700,1840 7750,1890 P3.4@7770,1890
RST_4: P4.4 R634.1 | length 76.4
  Bottom Layer w10: P4.4@3530,1480 R634.1@3606.38,1480
SCI_RX0: J600.76 R646.1 | length 1505.4
  Top Layer w10: v1(510,1020) R646.1@556.38,1020
  Signal Layer 4 w10: v1(510,1020) 510,150 580,80 v1(1070,80)
SCI_TX0: J600.78 R644.1 | length 1627.3
  Top Layer w10: v1(510,1120) R644.1@556.38,1120
  Signal Layer 4 w10: v1(510,1120) 510,1110 487.13,1087.13 487.13,137.87 575,50 v1(1040,50)
SGND2: C616.1 J603.1 U602.9 U602.15 | length 539.1
  Bottom Layer w20: C616.1@170,1158.5 186.5,1175 U602.15@252.99,1175 ; U602.9@252.99,875 305,875 320,890 320,1132.35 297.66,1154.68 273.31,1154.68 U602.15@252.99,1175 ; v1(300,1170) 295,1175 U602.15@252.99,1175
SiC_F1: P1.1 R618.2 | length 4285.7
  Top Layer w10: R618.2@1000,503.62 1000,530 1010,540 v1(1320,540)
  Signal Layer 4 w10: v1(1320,540) 1320,800 2240,1720 4560,1720 4570,1730 P1.1@4570,1770
SiC_F2: P2.1 R620.2 | length 6068.2
  Top Layer w10: R620.2@870,493.62 870,550 882.87,562.87 1437.13,562.87 v1(1440,560)
  Signal Layer 4 w10: v1(1440,560) 1440,808.5 2280,1648.5 6148.5,1648.5 6170,1670 P2.1@6170,1770
SiC_F3: P3.1 R624.2 | length 7823.9
  Top Layer w10: R624.2@760,493.62 760,570 772.87,582.87 1557.13,582.87 v1(1560,580)
  Signal Layer 4 w10: v1(1560,580) 1560,816.38 2320,1576.38 7746.38,1576.38 7770,1600 P3.1@7770,1770
SiC_F4: P4.1 R635.2 | length 3020.1
  Top Layer w10: v1(1048.19,510) v1(1650,510)
  Signal Layer 4 w10: v1(1650,510) 1650,824.72 2347.4,1522.13 3387.87,1522.13 P4.1@3430,1480
  Bottom Layer w10: v1(1048.19,510) 1056.38,510 R635.2@1050,503.62
VDD: C35.1 D1.1 R39.1 U1.2 | length 516
  Bottom Layer w20: D1.1@230,1818.74 238.74,1818.74 260,1840 v1(400,1840) 632.91,1840 R39.1@632.91,1830 632.91,1739.84 C35.1@630,1736.93
VREFHI: J600.45
pads on no net: FID1.1 FID2.1 FID3.1 J600.1 J600.2 J600.3 J600.4 J600.5 J600.6 J600.8 J600.9 J600.11 J600.13 J600.14 J600.16 J600.23 J600.26 J600.27 J600.28 J600.29 J600.30 J600.31 J600.32 J600.33 J600.34 J600.36 J600.37 J600.39 J600.40 J600.41 J600.42 J600.43 J600.44 J600.62 J600.63 J600.66 J600.68 J600.70 J600.71 J600.72 J600.73 J600.75 J600.81 J600.82 J600.85 J600.86 J600.87 J600.88 J600.89 J600.90 J600.91 J600.92 J600.93 J600.94 J600.95 J600.96 J600.99 J600.100 J600.101 J600.102 J600.103 J600.104 J600.105 J600.106 J600.107 J600.108 J600.109 J600.110 J600.113 J600.114 J600.115 J600.116 J600.117 J600.118 J600.119 J600.120 J600.181 J600.182 J600.185 J600.186 J602.MP1 J602.MP2 J603.2 J603.MP1 J603.MP2 L100.1 L100.3 L101.1 L101.3 L102.1 L102.3 T1.4 T1.6 T1.7 T1.8 T1.9 T1.10 U2.6 U103.4 U203.4 U600.1 U601.7 U602.6 U602.7 U602.10 U602.11

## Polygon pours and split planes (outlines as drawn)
AC_L on Top Layer "Signal Layer 1-No Net 3" (solid, remove dead copper, pour order 380): 3810,1900 3790,1920 3790,2040 3790,2890 4070,2890 4070,2090 4020,2030 4020,1920 4000,1900
PGND on Top Layer "Top Layer-No Net 13" (solid, remove dead copper, pour order 364): 3800,10 3750,10 3700,70 3700,620 3750,663 4420,663 4420,10 3820,10
AC_L on Top Layer "Top Layer-No Net 12" (solid, remove dead copper, pour order 336): 2820,3040 2820,3220 2860,3260 7920,3260 7960,3230 7960,2910 7880,2830 3230,2830 3180,2880 3140,2920 3080,2980 2880,2980
AC_N on Top Layer "Top Layer-No Net 7" (solid, pour order 114): 2200,1281.1 2710,1280 2770,1220 2840,1150 3130,1150 3180,1100 3180,610 3070,500 2350,500 2320,530 2320,730 2280,770 2200,770 2170,800 2170,1251.1
PGND on Top Layer "Bottom Layer-No Net 2" (solid, pour order 268): 8900,2327.93 9202.07,2327.93 9230,2300 9230,2010 8740,2010 8870,2140 8870,2300
PGND on Top Layer "Bottom Layer-No Net 1" (solid, pour order 266): 5670,2150 5670,2300 5690,2320 5990,2320 6010,2300 6010,2150 6010,2030 5550,2030
PGND on Top Layer "Bottom Layer-No Net 1" (solid, pour order 264): 7270,2150 7270,2290 7300,2320 7580,2320 7610,2290 7610,2030 7150,2030
PGND on Top Layer "Signal Layer 1-No Net" (solid, remove dead copper, pour order 262): 9150,2058.58 9230,2010 9230,490 8750,10 4270,10 4230,50 4230,2010 4278.58,2058.58
PGND on Top Layer "Top Layer-No Net 10" (solid, remove dead copper, pour order 176): 480.56,30 510,9.9 3410.1,9.9 3433.01,40 3433.01,422.8 3393.01,462.8 1933.01,462.8 1893.01,502.8 1893.01,600.56 1851.16,632.8 510,630 480.56,600.56
NetL100_4 on Top Layer "Top Layer-No Net 9" (solid, pour order 146): 4880,2190 4960,2110 5510,2110 5600,2200 5600,2550 5580,2570 5110,2570 5080,2540 5080,2420 5050,2390 4900,2390 4880,2370
NetL101_4 on Top Layer "Top Layer-No Net 3" (solid, pour order 144): 6480,2190 6560,2110 7120,2110 7200,2190 7200,2310 7240,2350 7270,2380 7270,2550 7250,2570 6670,2570 6650,2550 6650,2410 6630,2390 6500,2390 6480,2370
NetL102_4 on Top Layer "Top Layer-No Net 4" (solid, remove dead copper, pour order 142): 17 vertices, not listed, extent 8080,2130 9040,2570
NetC113_2 on Top Layer "Top Layer-No Net 6" (solid, pour order 130): 2830,2350 3600,2350 3650,2300 3650,2090 3600,2040 2850,2040 2790,2100 2790,2300
PFC_4H_S on Top Layer "Top Layer-No Net 2" (solid, pour order 126): 3210,660 3380,660 3400,680 3400,881.25 3380,910 3210,910 3190,881.25 3190,680
NetC113_2 on Top Layer "Top Layer-No Net 8" (solid, pour order 116): 3280,2300 3310,2270 3310,2250 3310,1250 3280,1220 2820,1220 2790,1250 2790,2260 2830,2300
NetL102_2 on Top Layer "Bottom Layer-No Net" (solid, pour order 90): 7675,3250 7755,3330 7935,3330 7960,3305 7960,3115 7945,3100 7695,3100 7675,3120
NetL101_2 on Top Layer "Bottom Layer-No Net" (solid, pour order 64): 5905,3250 5985,3330 6165,3330 6190,3305 6190,3115 6175,3100 5925,3100 5905,3120
NetL100_2 on Top Layer "Bottom Layer-No Net" (solid, pour order 56): 4115,3250 4195,3330 4375,3330 4400,3305 4400,3115 4385,3100 4135,3100 4115,3120
AC_N on Top Layer "Top Layer-No Net 2" (solid, pour order 50): 2990,660 3160,660 3180,680 3180,872.74 3140,890 3010,890 2970,872.74 2970,680
NetC107_1 on Top Layer "Top Layer-No Net" (solid, pour order 20): 1580,3270 1630,3320 2700,3320 2750,3270 2750,3040 2700,2990 1630,2990 1580,3040
NetF100_2 on Top Layer "Top Layer-No Net 1" (solid, pour order 24): 20,3290 50,3320 290,3320 340,3280 340,3070 310,3040 150,3040 120,3010 120,2990 100,2960 30,2960 20,2970
NetC109_1 on Top Layer "Top Layer-No Net" (solid, pour order 26): 200,3240 250,3280 1280,3280 1330,3240 1330,2870 1280,2820 250,2820 200,2880
NetC110_2 on Top Layer "Top Layer-No Net" (solid, pour order 30): 1580,2300 1630,2350 2670,2350 2720,2300 2720,2050 2670,2000 1630,2000 1580,2050
NetC109_2 on Top Layer "Top Layer-No Net" (solid, pour order 188): 20,2300 70,2350 1280,2350 1330,2300 1330,2050 1310,2030 40,2030 20,2050
EARTH0 on Top Layer "Top Layer-No Net 11" (solid, pour order 190): 1560,2740 2940,2740 2970,2710 2970,2640 2940,2610 1560,2610 1530,2640 1530,2710
PGND on Bottom Layer "Bottom Layer-No Net 8" (solid, pour order 334): 9100,2430 9100,2327.93 8900,2327.93
PGND on Bottom Layer "Bottom Layer-No Net 6" (solid, pour order 332): 7840,2610 7870,2580 9200,2580 9230,2610 9230,2750 9200,2780 7920,2780 7840,2700
PGND on Bottom Layer "Bottom Layer-No Net 7" (solid, remove dead copper, pour order 330): 7270,2530 7221.32,2600 7500,2600 7610,2380 7610,2080.24 7270,2080.24
PGND on Bottom Layer "Bottom Layer-No Net 6" (solid, pour order 328): 6210,2600 6240,2570 7460,2570 7500,2600 7500,2740 7460,2770 6240,2770 6210,2740
PGND on Bottom Layer "Bottom Layer-No Net 10" (solid, remove dead copper, pour order 326): 7270,2150 7270,2270 7300,2300 7580,2300 7610,2270 7610,2150 7610,2030 7150,2030
PGND on Bottom Layer "Bottom Layer-No Net 10" (solid, pour order 324): 5670,2150 5670,2270 5700,2300 5980,2300 6010,2270 6010,2150 6010,2030 5550,2030
PGND on Bottom Layer "Bottom Layer-No Net 6" (solid, pour order 180): 4630,2600 4660,2570 5870,2570 5900,2600 5900,2740 5870,2770 4660,2770 4630,2740
PGND on Bottom Layer "Bottom Layer-No Net 7" (solid, pour order 182): 5670,2530 5621.32,2600 5900,2600 6010,2380 6010,2080.24 5670,2080.24
AC_L on Bottom Layer "Bottom Layer-No Net" (solid, pour order 322): 4188.63,3070.57 4208.63,3090.56 4381.78,3090.56 4399.16,3080.13 4399.16,2950.13 4378.9,2929.87 4208.63,2929.87 4188.63,2950.13
NetL102_4 on Bottom Layer "Top Layer-No Net 4" (solid, remove dead copper, pour order 312): 17 vertices, not listed, extent 8080,2130 9030,2570
NetL101_4 on Bottom Layer "Top Layer-No Net 3" (solid, remove dead copper, pour order 300): 6480,2190 6560,2110 7120,2110 7200,2190 7200,2310 7240,2350 7270,2380 7270,2550 7250,2570 6670,2570 6650,2550 6650,2410 6630,2390 6500,2390 6480,2370
NetL100_4 on Bottom Layer "Top Layer-No Net 9" (solid, remove dead copper, pour order 280): 4880,2190 4960,2110 5510,2110 5600,2200 5600,2550 5580,2570 5110,2570 5080,2540 5080,2420 5050,2390 4900,2390 4880,2370
NetC110_2 on Bottom Layer "Top Layer-No Net" (solid, pour order 248): 1580,2300 1630,2350 2670,2350 2720,2300 2720,2050 2670,2000 1630,2000 1580,2050
NetC109_2 on Bottom Layer "Top Layer-No Net" (solid, pour order 234): 20,2300 70,2350 1280,2350 1330,2300 1330,2050 1280,2000 70,2000 20,2050
NetC109_1 on Bottom Layer "Top Layer-No Net" (solid, remove dead copper, pour order 212): 200,3240 250,3280 1280,3280 1330,3240 1330,2870 1280,2820 250,2820 200,2880
NetF100_2 on Bottom Layer "Top Layer-No Net 1" (solid, pour order 192): 20,3290 50,3320 290,3320 340,3280 340,3070 310,3040 150,3040 120,3010 120,2990 100,2960 30,2960 20,2970
PGND on Bottom Layer "Bottom Layer-No Net 5" (solid, remove dead copper, pour order 178): 110.7,1450 170.7,1400 1440,1400 1460.7,1476.61 1479.67,1538.98 1500.7,1560 1500.7,1770 1460.7,1770 140.7,1770 110.7,1740
PGND on Bottom Layer "Bottom Layer-No Net 4" (solid, remove dead copper, pour order 174): 17 vertices, not listed, extent 520,10 4270,1810
PGND on Bottom Layer "Bottom Layer-No Net 3" (solid, pour order 172): 3850,90 3850,590 3880,620 4150,620 4230,700 4246.69,700 4249.92,703.23 4249.92,59.13 4250,59.05 3880.95,59.05
PGND on Bottom Layer "Bottom Layer-No Net 2" (solid, pour order 170): 8900,2327.93 9150,2327.93 9230,2260 9230,2010 8740,2010 8870,2140 8870,2300
PGND on Bottom Layer "Signal Layer 1-No Net" (solid, remove dead copper, pour order 160): 9150,2058.58 9230,2010 9230,490 8750,10 4250,10 4235,25 4230,2010 4278.58,2058.58
AC_L on Bottom Layer "Bottom Layer-No Net" (solid, remove dead copper, pour order 80): 7749.6,3070.57 7769.6,3090.56 7942.75,3090.56 7960.13,3080.13 7960.13,2950.13 7939.87,2929.87 7769.6,2929.87 7749.6,2950.13
AC_L on Bottom Layer "Bottom Layer-No Net" (solid, remove dead copper, pour order 78): 5979.6,3070.57 5999.6,3090.56 6172.75,3090.56 6190.13,3080.13 6190.13,2950.13 6169.87,2929.87 5999.6,2929.87 5979.6,2950.13
NetL102_2 on Bottom Layer "Bottom Layer-No Net" (solid, pour order 46): 7675,3250 7755,3330 7935,3330 7960,3305 7960,3115 7945,3100 7695,3100 7675,3120
NetL101_2 on Bottom Layer "Bottom Layer-No Net" (solid, pour order 44): 5905,3250 5985,3330 6165,3330 6190,3305 6190,3115 6175,3100 5925,3100 5905,3120
NetL100_2 on Bottom Layer "Bottom Layer-No Net" (solid, pour order 38): 4115,3250 4195,3330 4375,3330 4400,3305 4400,3115 4385,3100 4135,3100 4115,3120
PGND on Bottom Layer "Bottom Layer-No Net 9" (solid, pour order 186): 9230,2640 9230,2150 9220,2160 9080,2160 9080,2640
PGND on Bottom Layer "Bottom Layer-No Net 11" (solid, pour order 356): 3220,1950 3250,2000 3349.12,2000 3359.9,2000 3400,1959.9 3400,1745.47 3223.76,1745.47 3217.98,1751.26
PGND on Bottom Layer "Bottom Layer-No Net 12" (solid, remove dead copper, pour order 358): 3170,1755.75 3450,1755.75 3450,1767.95 3390,1827.95 3230,1827.95
NetC107_1 on Bottom Layer "Top Layer-No Net" (solid, pour order 394): 1580,3270 1630,3320 2700,3320 2750,3270 2750,3040 2700,2990 1630,2990 1580,3040
PGND on Signal Layer 3 "Signal Layer 3-No Net 1" (solid, remove dead copper, pour order 318): 22 vertices, not listed, extent 480,10 3460,1770
PGND on Signal Layer 3 "Signal Layer 3-No Net 2" (solid, remove dead copper, pour order 320): 4320,1770 4490,1940 8090,1940 8170,1860 8170,1167 8070,1067 3297,1067 2920,1444 2920,1770
NetL102_4 on Signal Layer 3 "Top Layer-No Net 4" (solid, remove dead copper, pour order 308): 17 vertices, not listed, extent 8080,2130 9040,2570
NetL101_4 on Signal Layer 3 "Top Layer-No Net 3" (solid, pour order 296): 6480,2190 6560,2110 7120,2110 7200,2190 7200,2310 7240,2350 7270,2380 7270,2550 7250,2570 6670,2570 6650,2550 6650,2410 6630,2390 6500,2390 6480,2370
NetL100_4 on Signal Layer 3 "Top Layer-No Net 9" (solid, remove dead copper, pour order 286): 4880,2190 4960,2110 5510,2110 5600,2200 5600,2550 5580,2570 5110,2570 5080,2540 5080,2420 5049.92,2390 4900,2390 4880.08,2370
NetC110_2 on Signal Layer 3 "Top Layer-No Net" (solid, pour order 252): 1580,2300 1630,2350 2670,2350 2720,2300 2720,2050 2670,2000 1630,2000 1580,2050
NetC109_2 on Signal Layer 3 "Top Layer-No Net" (solid, pour order 242): 20,2300 70,2350 1280,2350 1330,2300 1330,2050 1280,2000 70,2000 20,2050
EARTH0 on Signal Layer 3 "Top Layer-No Net 11" (solid, pour order 228): 1560,2740 2940,2740 2970,2710 2970,2640 2940,2610 1560,2610 1530,2640 1530,2710
NetC109_1 on Signal Layer 3 "Top Layer-No Net" (solid, pour order 208): 200,3240 250,3280 1280,3280 1330,3240 1330,2870 1280,2820 250,2820 200,2880
NetF100_2 on Signal Layer 3 "Top Layer-No Net 1" (solid, pour order 198): 20,3290 50,3320 290,3320 340,3280 340,3070 310,3040 150,3040 120,3010 120,2990 100,2960 30,2960 20,2970
AC_L on Signal Layer 3 "Top Layer-No Net 5" (solid, pour order 136): 2820,3040 2820,3220 2860,3260 7920,3260 7960,3230 7960,2910 7880,2830 3230,2830 3180,2880 3140,2920 3080,2980 2880,2980
NetL102_2 on Signal Layer 3 "Bottom Layer-No Net" (solid, pour order 94): 7675,3250 7755,3330 7935,3330 7960,3305 7960,3115 7945,3100 7695,3100 7675,3120
NetL101_2 on Signal Layer 3 "Bottom Layer-No Net" (solid, pour order 68): 5905,3250 5985,3330 6165,3330 6190,3305 6190,3115 6175,3100 5925,3100 5905,3120
NetL100_2 on Signal Layer 3 "Bottom Layer-No Net" (solid, pour order 58): 4115,3250 4195,3330 4375,3330 4400,3305 4400,3115 4385,3100 4135,3100 4115,3120
AC_L on Signal Layer 3 "Signal Layer 1-No Net 3" (solid, remove dead copper, pour order 354): 3810,1900 3790,1920 3790,2040 3790,2890 4070,2890 4070,2090 4020,2030 4020,1920 4000,1900 4020,1920 4000,1900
